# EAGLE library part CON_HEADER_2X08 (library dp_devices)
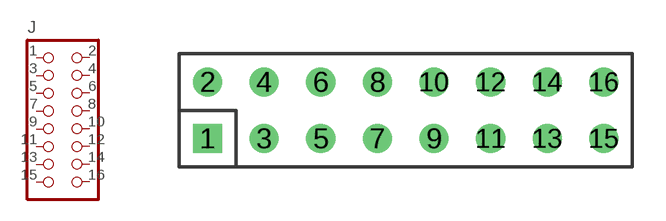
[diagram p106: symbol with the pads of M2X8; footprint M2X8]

Designator prefix J

## CON_HEADER_2X08  [M2X8]
1  1  pas
2  2  pas
3  3  pas
4  4  pas
5  5  pas
6  6  pas
7  7  pas
8  8  pas
9  9  pas
10  10  pas
11  11  pas
12  12  pas
13  13  pas
14  14  pas
15  15  pas
16  16  pas

## Footprint M2X8 (pad centres in mm)
drill 0.8 square: 1 -8.89,-1.27
drill 0.8 round: 2 -8.89,1.27; 3 -6.35,-1.27; 4 -6.35,1.27; 5 -3.81,-1.27; 6 -3.81,1.27; 7 -1.27,-1.27; 8 -1.27,1.27; 9 1.27,-1.27; 10 1.27,1.27; 11 3.81,-1.27; 12 3.81,1.27; 13 6.35,-1.27; 14 6.35,1.27; 15 8.89,-1.27; 16 8.89,1.27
